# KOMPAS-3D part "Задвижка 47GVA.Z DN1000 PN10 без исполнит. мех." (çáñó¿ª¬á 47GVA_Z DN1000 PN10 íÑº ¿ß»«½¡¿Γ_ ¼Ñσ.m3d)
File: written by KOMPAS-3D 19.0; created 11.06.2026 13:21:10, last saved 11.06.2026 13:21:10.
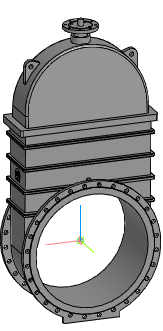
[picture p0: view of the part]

Document properties: Автор: Евгений; Полное имя файла: Z:\3.Личные\kachalov\001_3d для проектировщиков\2.2 Тип 47GVA, 47GVA.Z\_stp\_stp_Задвижка 47GVA.Z DN350-DN1200 без исп.мех\Задвижка 47GVA_Z DN1000 PN10 без исполнит_ мех.m3d

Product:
- Part/product: Задвижка 47GVA.Z DN1000 PN10 без исполнит. мех.

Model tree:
1. Операция без истории:1  (labels: Задвижка 47GVA.Z DN1000 PN10 без исполнит. мех.)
